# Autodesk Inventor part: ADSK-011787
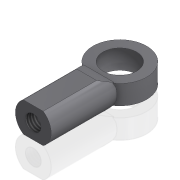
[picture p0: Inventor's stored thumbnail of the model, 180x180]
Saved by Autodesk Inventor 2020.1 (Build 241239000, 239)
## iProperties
Created: 1999-12
Part Number: ADSK-011787
Material: Acier (alliage faible hypertrempé)
Document SubType Name: Modeling
Designer: gpurviance
Density: 7.84 g/cm^3
Appearance: Metal-Steel(Polish)
Mass: 81.7978 g
Surface Area: 51.4307 cm^2
Volume: 10.4334 cm^3
Control State: 0
Master: False
Checked Out: False
Shininess: 0.0
Length Units: 11269
Angle Units: 11279
Time Units: 11290
Mass Units: 11283
Length Display Precision: 3
Angle Display Precision: 2
Compacted: True
Dimensions: 28,6x15,9x60,3 mm
Mass: 0,082 kg
Density: 0.0
Volumn: 0.0
Area: 0.0
PropertySet Name: Model Information
Author: gpurviance
Revision Number: -
Title: ADSK-011787
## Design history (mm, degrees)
node "Extrusion1" dims "d4" = 34.925, "d5" = 0
workplane "Work Plane1"
node "Revolution1" dims "d11" = 90 deg
node "Hole1" dims "d12" = 8.376, "d13" = 9.525, "d14" = 6.35, "d15" = 60 deg, "d16" = 27.3, "d17" = 118 deg, "d21" = 20
node "Extrusion2" dims "d19" = 31.75, "d20" = 0
node "Solide1"
node "Corps solides"
node "Corps surfaciques"
sketch "Sketch1"
  geometry: L1 (-9.525, 7.938)-(11.112, 7.938); L2 (11.112, -7.937)-(-9.525, -7.938); A1 r 9.525 centre (0, 0) between (5.265, -7.937) and (5.265, 7.938); A2 r 9.525 centre (0, 0) between (-5.265, 7.938) and (-5.265, -7.938)
  constraints: 4 end point, 4 point on circle, 4 point on line, 2 centre point, 1 concentric, 1 horizontal, 1 parallel, 1 other
  dimensions: "d1" = 7.9375 distance from line of A1.centre L2 (= 0.5 x d2); "d2" = 15.875 distance between parallel lines of L1 L2; "d3" = 9.525 radius of A1
sketch "Sketch3"
  geometry: L1 (-5.265, 7.938)-(5.265, 7.938) reference; L2 (5.265, -7.938)-(-5.265, -7.937) reference; L3 (0, -7.938)-(0, 7.938); L4 (0, 0)-(-6.35, 0); L5 (-14.288, 5.159)-(-14.287, -5.159); L6 (-14.287, -5.159)-(-8.936, -5.159); L7 (-14.288, 5.159)-(-8.936, 5.159); A1 r 10.319 centre (0, 0) between (-8.936, 5.159) and (-8.936, -5.159)
  constraints: 10 end point, 3 midpoint, 2 perpendicular, 2 point on circle, 1 centre point, 1 coincident
  dimensions: "d7" = 10.31875 radius of A1; "d8" = 14.2875 distance between parallel lines of L3 L5; "d9" = 10.31875 distance between parallel lines of L7 L6; "d10" = 5.15938 distance between parallel lines of L6 L4 (= 0.5 x d9)
sketch "Sketch4"
  geometry: A1 r 9.525 centre (0, 0) between (-5.265, 7.938) and (-5.265, -7.938) reference; 1 further point
  constraints: 1 coincident
sketch "Sketch6"
  geometry: L1 (5.159, -25.4)-(5.159, 0.721) reference; L2 (-5.159, -25.4)-(-5.159, 0.721) reference; L3 (7.938, 0)-(7.938, 34.925) reference; L4 (-7.938, 0)-(-7.938, 34.925) reference; L5 (7.938, 6.55)-(5.159, 0); L6 (-5.159, 0)-(-7.938, 6.458); L7 (7.938, 6.55)-(16.052, 6.55); L8 (16.052, 6.55)-(16.052, -2.399); L9 (16.052, -2.399)-(7.938, -2.399); L10 (7.938, -2.399)-(5.159, 0); L11 (-5.159, 0)-(-8.118, -2.399); L12 (-8.118, -2.399)-(-15.775, -2.399); L13 (-15.775, -2.399)-(-15.775, 6.458); L14 (-15.775, 6.458)-(-7.938, 6.458)
  constraints: 20 end point, 4 point on line, 3 perpendicular, 2 parallel, 1 collinear
other parameters: "d0" = 19.05, "d6" = 11.1125
